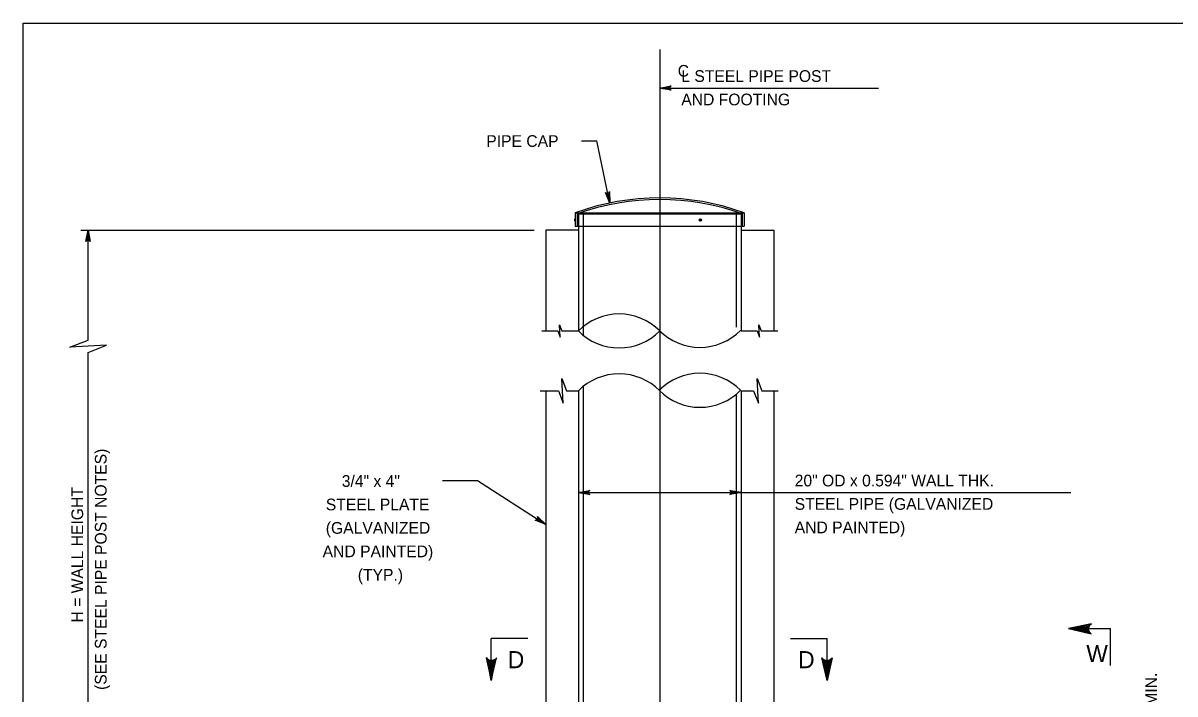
# Model space of a CAD drawing. Extents: x 3475 to 6558, y -3780 to 1166.
# Drawn here: x 4642.3 to 4944.3, y -2589.2 to -2413.3 of the extents above; entities that cross this region are included whole.
import ezdxf

# ---------------------------------------------------------------- set-up
doc = ezdxf.new("R2010")
doc.units = 0
doc.layers.add('1', color=7, linetype='Continuous')
doc.layers.add('2', color=7, linetype='Continuous')

msp = doc.modelspace()

# ---------------------------------------------------------------- linework, layer by layer
at = {"layer": '1'}
for p, q in [((4809.25, -2420.25), (4809.25, -2638.9)), ((4809.25, -2430.36), (4866.61, -2430.36)), ((4788.69, -2444.17), (4792.79, -2444.17)), ((4796.17, -2460.48), (4792.79, -2444.17)), ((4787.1, -2463.06), (4787.1, -2466.51)), ((4787.1, -2463.06), (4831.4, -2463.06)), ((4787.61, -2463.31), (4787.61, -2466.51)), ((4787.92, -2463.31), (4830.58, -2463.31)), ((4787.92, -2463.31), (4787.92, -2466.51)), ((4789.19, -2463.57), (4789.19, -2495.02)), ((4829.32, -2463.31), (4829.32, -2492.98)), ((4830.58, -2463.31), (4830.58, -2466.51)), ((4830.89, -2463.31), (4830.89, -2466.51)), ((4831.4, -2463.06), (4831.4, -2466.51)), ((4787.1, -2466.51), (4831.4, -2466.51)), ((4787.92, -2466.51), (4787.92, -2494)), ((4819.92, -2465.22), (4819.92, -2464.6)), ((4830.58, -2466.51), (4830.58, -2494)), ((4657.49, -2467.58), (4776.33, -2467.58)), ((4659.39, -2496.46), (4659.39, -2467.58)), ((4787.92, -2467.58), (4779.39, -2467.58)), ((4779.39, -2467.58), (4779.39, -2494)), ((4830.58, -2467.58), (4839.11, -2467.58)), ((4839.11, -2467.58), (4839.11, -2494)), ((4778.32, -2494), (4782.5, -2494)), ((4783.56, -2494), (4787.92, -2494)), ((4830.58, -2494), (4834.76, -2494)), ((4835.83, -2494), (4840.18, -2494)), ((4659.39, -2738.99), (4659.39, -2499.66)), ((4789.19, -2508.56), (4789.19, -2719.79)), ((4777.92, -2509.71), (4782.67, -2509.71)), ((4779.39, -2509.71), (4779.39, -2608.86)), ((4784.81, -2509.71), (4787.92, -2509.71)), ((4787.92, -2509.71), (4787.92, -2719.79)), ((4829.32, -2510.6), (4829.32, -2719.79)), ((4830.58, -2509.71), (4830.58, -2719.79)), ((4830.58, -2509.71), (4833.83, -2509.71)), ((4835.97, -2509.71), (4840.26, -2509.71)), ((4839.12, -2509.71), (4839.12, -2608.86)), ((4752.28, -2533.24), (4761.48, -2533.24)), ((4761.48, -2533.24), (4779.39, -2544.76)), ((4787.92, -2536.35), (4917.01, -2536.35)), ((4916.41, -2572.02), (4927.42, -2572.02)), ((4927.42, -2581.67), (4927.42, -2572.02)), ((4774.7, -2574.63), (4765.05, -2574.63)), ((4765.05, -2585.63), (4765.05, -2574.63)), ((4843.51, -2574.63), (4853.16, -2574.63)), ((4853.16, -2585.63), (4853.16, -2574.63))]:
    msp.add_line(p, q, dxfattribs=at)
for points in [[(4809.25, -2430.36), (4812.23, -2429.8), (4812, -2429.96), (4811.89, -2430.16), (4811.85, -2430.36), (4811.89, -2430.56), (4812, -2430.76), (4812.23, -2430.91), (4809.25, -2430.36), (4812, -2430.76), (4811.89, -2430.56), (4809.25, -2430.36), (4811.85, -2430.36), (4811.89, -2430.16), (4809.25, -2430.36), (4812, -2429.96)], [(4796.17, -2460.48), (4795.01, -2457.68), (4795.22, -2457.87), (4795.44, -2457.94), (4795.64, -2457.94), (4795.83, -2457.86), (4796, -2457.71), (4796.11, -2457.45), (4796.17, -2460.48), (4796, -2457.71), (4795.83, -2457.86), (4796.17, -2460.48), (4795.64, -2457.94), (4795.44, -2457.94), (4796.17, -2460.48), (4795.22, -2457.87)], [(4659.39, -2467.58), (4659.95, -2470.56), (4659.79, -2470.33), (4659.59, -2470.21), (4659.39, -2470.18), (4659.19, -2470.21), (4658.99, -2470.33), (4658.83, -2470.56), (4659.39, -2467.58), (4658.99, -2470.33), (4659.19, -2470.21), (4659.39, -2467.58), (4659.39, -2470.18), (4659.59, -2470.21), (4659.39, -2467.58), (4659.79, -2470.33)], [(4782.5, -2494), (4783.15, -2495.6), (4782.95, -2492.4), (4783.56, -2494)], [(4834.76, -2494), (4835.41, -2495.6), (4835.22, -2492.4), (4835.83, -2494)], [(4659.39, -2499.66), (4664.19, -2497.72), (4654.59, -2498.3), (4659.39, -2496.46)], [(4782.67, -2509.71), (4783.97, -2512.91), (4783.59, -2506.51), (4784.81, -2509.71)], [(4833.83, -2509.71), (4835.13, -2512.91), (4834.74, -2506.51), (4835.97, -2509.71)], [(4787.92, -2536.35), (4790.9, -2535.79), (4790.67, -2535.95), (4790.55, -2536.15), (4790.52, -2536.35), (4790.55, -2536.55), (4790.67, -2536.75), (4790.9, -2536.91), (4787.92, -2536.35), (4790.67, -2536.75), (4790.55, -2536.55), (4787.92, -2536.35), (4790.52, -2536.35), (4790.55, -2536.15), (4787.92, -2536.35), (4790.67, -2535.95)], [(4830.58, -2536.35), (4827.6, -2536.91), (4827.83, -2536.75), (4827.95, -2536.55), (4827.98, -2536.35), (4827.95, -2536.15), (4827.83, -2535.95), (4827.6, -2535.79), (4830.58, -2536.35), (4827.83, -2535.95), (4827.95, -2536.15), (4830.58, -2536.35), (4827.98, -2536.35), (4827.95, -2536.55), (4830.58, -2536.35), (4827.83, -2536.75)], [(4779.39, -2544.76), (4776.58, -2543.62), (4776.85, -2543.61), (4777.06, -2543.5), (4777.2, -2543.35), (4777.28, -2543.17), (4777.29, -2542.93), (4777.18, -2542.68), (4779.39, -2544.76), (4777.29, -2542.93), (4777.28, -2543.17), (4779.39, -2544.76), (4777.2, -2543.35), (4777.06, -2543.5), (4779.39, -2544.76), (4776.85, -2543.61)], [(4916.41, -2572.02), (4922.37, -2573.44), (4922.14, -2573.24), (4921.91, -2573.05), (4921.8, -2572.81), (4921.68, -2572.57), (4921.65, -2572.33), (4921.61, -2572.09), (4921.65, -2571.85), (4921.69, -2571.61), (4921.81, -2571.37), (4921.93, -2571.13), (4922.16, -2570.94), (4922.39, -2570.75), (4916.41, -2572.02), (4922.16, -2570.94), (4921.93, -2571.13), (4916.41, -2572.02), (4921.81, -2571.37), (4921.69, -2571.61), (4916.41, -2572.02), (4921.65, -2571.85), (4921.61, -2572.09), (4916.41, -2572.02), (4921.65, -2572.33), (4921.68, -2572.57), (4916.41, -2572.02), (4921.8, -2572.81), (4921.91, -2573.05), (4916.41, -2572.02), (4922.14, -2573.24)], [(4765.05, -2585.63), (4766.47, -2579.68), (4766.27, -2579.91), (4766.08, -2580.13), (4765.84, -2580.25), (4765.59, -2580.37), (4765.35, -2580.4), (4765.11, -2580.43), (4764.87, -2580.39), (4764.63, -2580.36), (4764.4, -2580.24), (4764.16, -2580.12), (4763.97, -2579.88), (4763.78, -2579.65), (4765.05, -2585.63), (4763.97, -2579.88), (4764.16, -2580.12), (4765.05, -2585.63), (4764.4, -2580.24), (4764.63, -2580.36), (4765.05, -2585.63), (4764.87, -2580.39), (4765.11, -2580.43), (4765.05, -2585.63), (4765.35, -2580.4), (4765.59, -2580.37), (4765.05, -2585.63), (4765.84, -2580.25), (4766.08, -2580.13), (4765.05, -2585.63), (4766.27, -2579.91)], [(4853.16, -2585.63), (4851.75, -2579.68), (4851.94, -2579.91), (4852.13, -2580.13), (4852.37, -2580.25), (4852.62, -2580.37), (4852.86, -2580.4), (4853.1, -2580.43), (4853.34, -2580.39), (4853.58, -2580.36), (4853.81, -2580.24), (4854.05, -2580.12), (4854.24, -2579.88), (4854.43, -2579.65), (4853.16, -2585.63), (4854.24, -2579.88), (4854.05, -2580.12), (4853.16, -2585.63), (4853.81, -2580.24), (4853.58, -2580.36), (4853.16, -2585.63), (4853.34, -2580.39), (4853.1, -2580.43), (4853.16, -2585.63), (4852.86, -2580.4), (4852.62, -2580.37), (4853.16, -2585.63), (4852.37, -2580.25), (4852.13, -2580.13), (4853.16, -2585.63), (4851.94, -2579.91)]]:
    msp.add_lwpolyline(points, dxfattribs=at)
msp.add_circle((4819.92, -2464.91), 0.308, dxfattribs=at)
for centre, radius, start, end in [((4809.25, -2523.65), 64.51, 69.9175, 110.0825), ((4809.25, -2523.54), 63.99, 70.2376, 109.7624), ((4787.18, -2464.91), 0.318, 104.9595, 255.0405), ((4798.59, -2504.53), 14.98, 44.6166, 135.3834), ((4798.59, -2483.48), 14.98, 224.6166, 315.3834), ((4819.78, -2483.33), 14.98, 224.6166, 315.3834), ((4798.59, -2520.23), 14.98, 44.6166, 135.3834), ((4819.78, -2520.09), 14.98, 44.6166, 135.3834), ((4819.78, -2499.04), 14.98, 224.6166, 315.3834)]:
    msp.add_arc(centre, radius, start, end, dxfattribs=at)
at = {"layer": '2'}
for p, q in [((4642.34, -2977.31), (4642.34, -2413.31)), ((4642.34, -2413.31), (5428.34, -2413.31))]:
    msp.add_line(p, q, dxfattribs=at)

# ---------------------------------------------------------------- texts
at = {"layer": '1'}
for s, height, p in [('C', 3.07, (4813.96, -2427.37)), ('L STEEL PIPE POST', 3.072, (4814.89, -2428.74)), ('AND FOOTING', 3.072, (4814.89, -2434.88)), ('PIPE CAP', 3.072, (4763.77, -2445.77)), ('3/4" x 4"', 3.072, (4725.89, -2534.88)), ('20" OD x 0.594" WALL THK.', 3.072, (4844.62, -2534.75)), ('STEEL PLATE', 3.072, (4721.71, -2541.03)), ('STEEL PIPE (GALVANIZED', 3.072, (4844.62, -2540.89)), ('(GALVANIZED', 3.072, (4721.7, -2547.17)), ('AND PAINTED)', 3.072, (4844.62, -2547.04)), ('AND PAINTED)', 3.072, (4720.88, -2553.32)), ('(TYP.)', 3.072, (4730.09, -2559.46)), ('D', 4.48, (4769.4, -2582.41)), ('D', 4.48, (4845.52, -2582.41)), ('W', 4.48, (4921.06, -2580.81))]:
    msp.add_text(s, height=height, dxfattribs=at).set_placement(p)
for s, p in [('(SEE STEEL PIPE POST NOTES)', (4664.25, -2588.1)), ('H = WALL HEIGHT', (4658.1, -2570.44)), ('6" MIN.', (4939.58, -2597.13))]:
    msp.add_text(s, height=3.072, rotation=90, dxfattribs=at).set_placement(p)

doc.saveas('drawing.dxf')
